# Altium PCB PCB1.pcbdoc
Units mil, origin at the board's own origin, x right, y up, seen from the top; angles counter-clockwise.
Board outline 3500 x 3430 mil, 2 copper layers (Top Layer, Bottom Layer), stack 62.2 mil thick; 73 components, 57 nets, 244 pads, 134 vias.
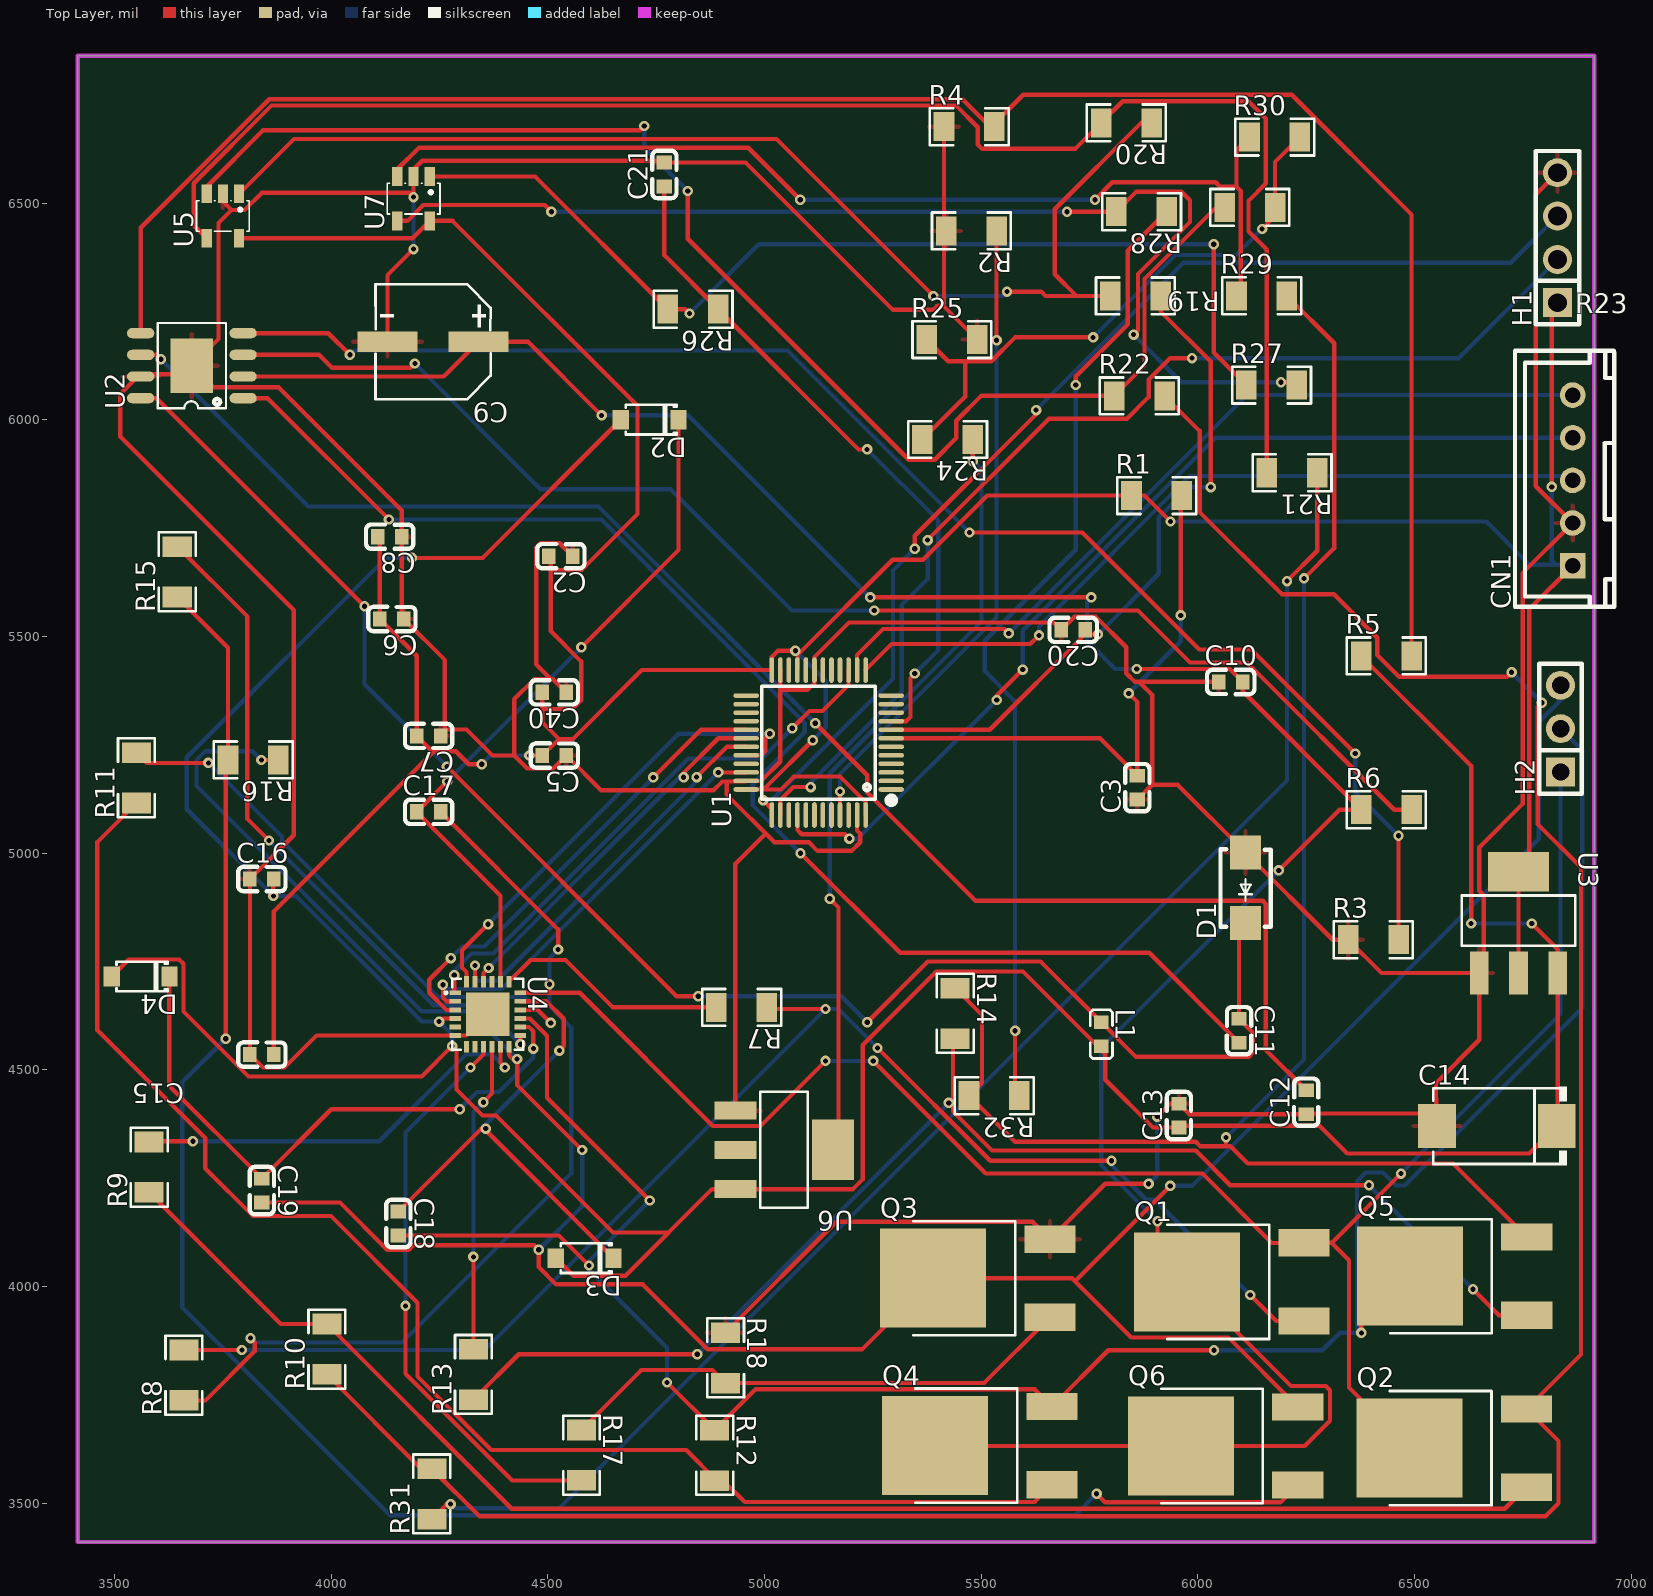
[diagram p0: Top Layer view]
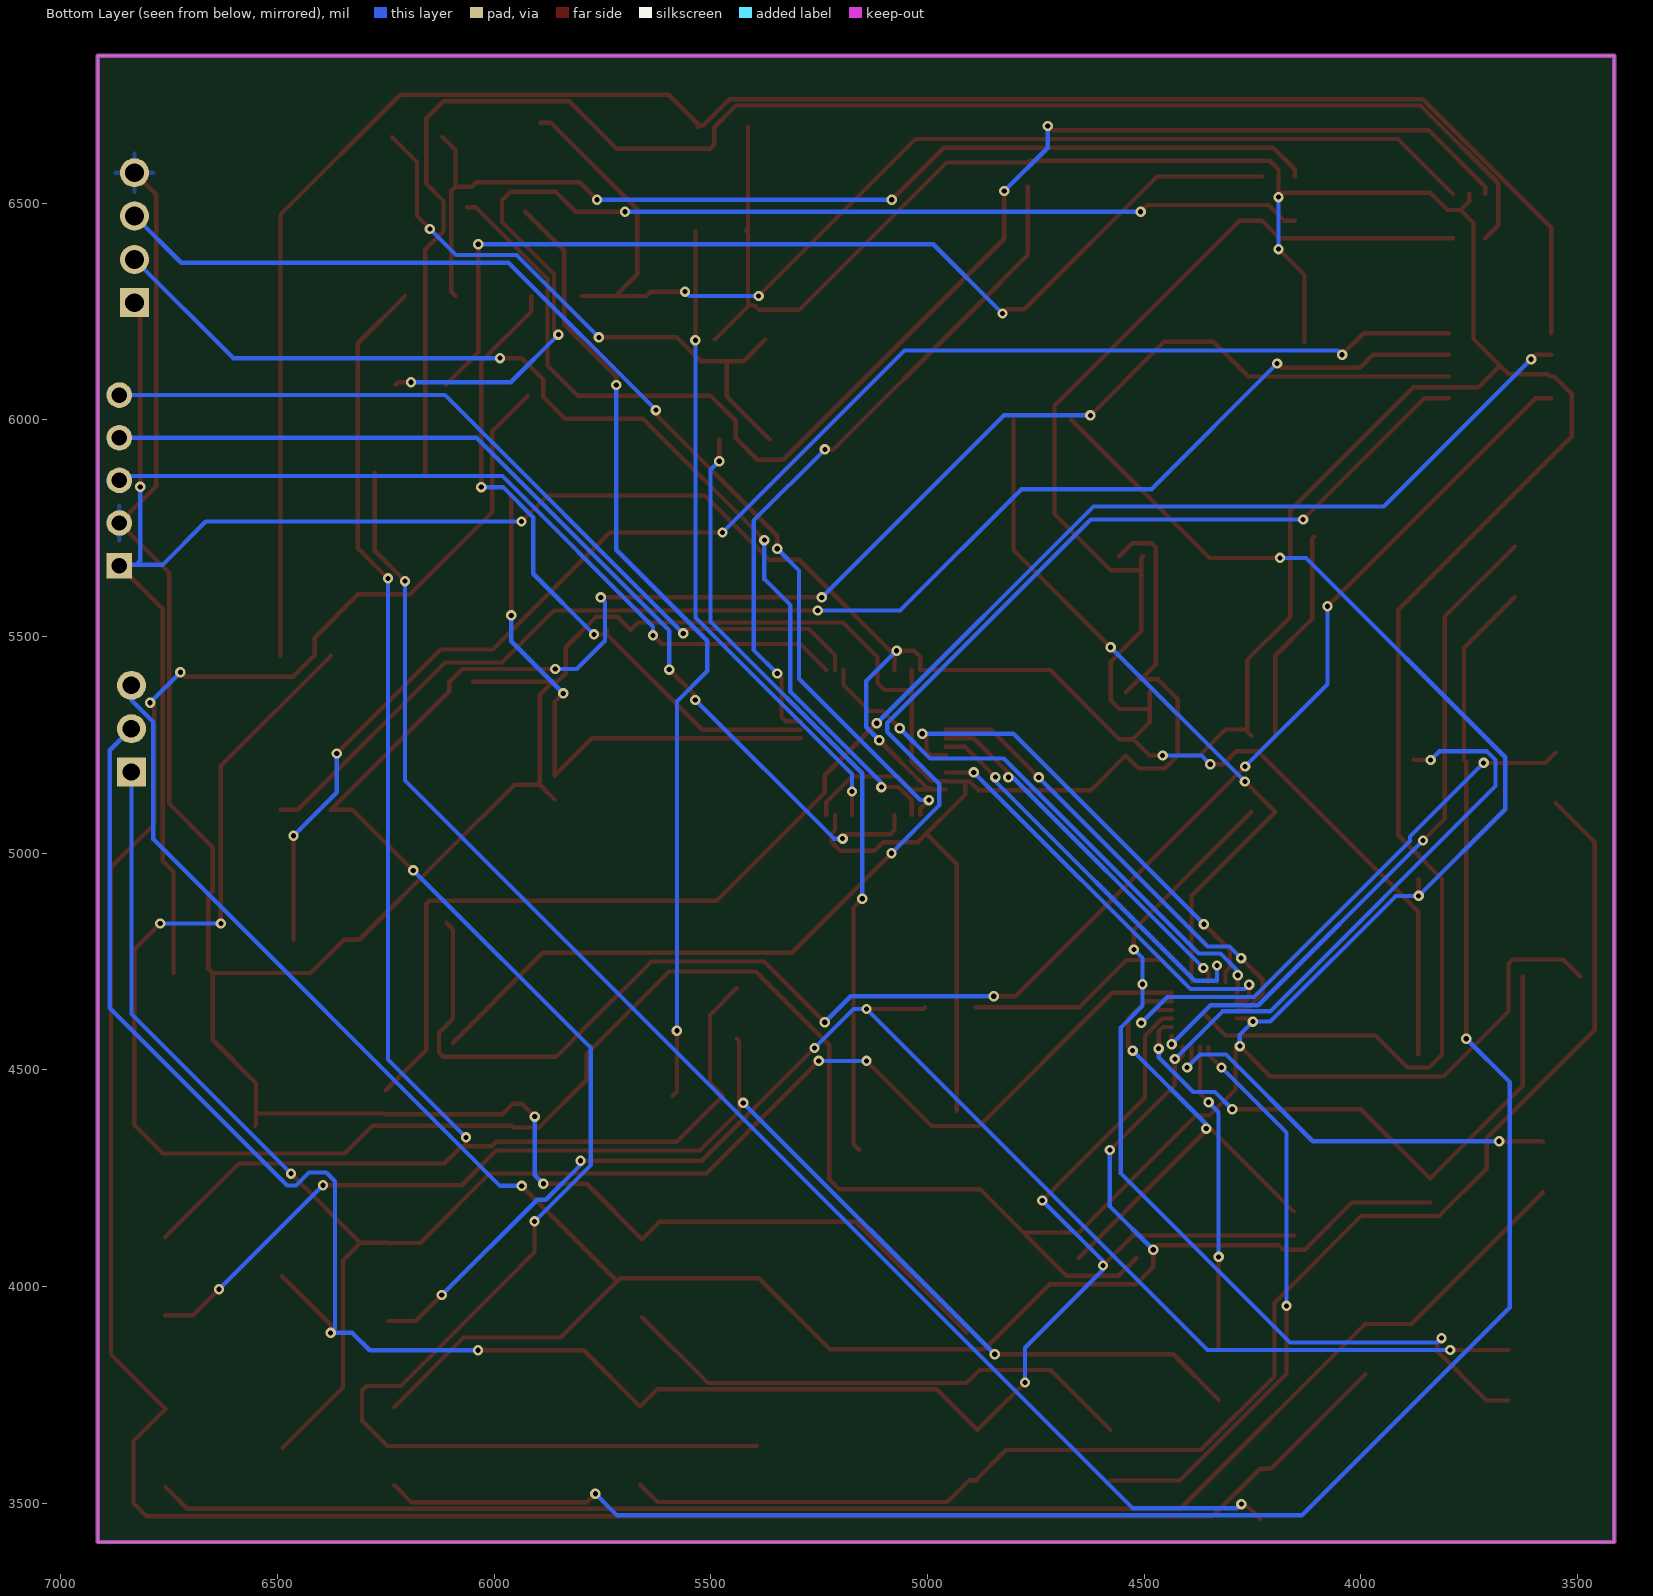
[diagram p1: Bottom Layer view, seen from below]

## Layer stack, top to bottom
Top Solder Mask Layer: solder mask 0.4, Dk 3.3
Top Layer: signal copper 1.4
Dielectric1: surface 59.4, FR4, Dk 4.5
Bottom Layer: signal copper 1.4
Bottom Solder Mask Layer: solder mask 0.4, Dk 3.3

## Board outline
3415,6840 3415,3410 6915,3410 6915,6840

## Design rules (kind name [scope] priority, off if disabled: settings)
BoardOutlineClearance copperThickness1oz [All] p0: genericclearance=10 ignorepadtopadclearanceinfootprint=FALSE except(0: Arc-SplitContinuation Track-SplitContinuation SMDPad-SplitContinuation THPad-SplitContinuation Via-SplitContinuation Fill-SplitContinuation Poly-SplitContinuation Region-SplitContinuation Text-SplitContinuation)
BoardOutlineClearance copperThickness2oz [All] p0: genericclearance=10 ignorepadtopadclearanceinfootprint=FALSE except(0: Arc-SplitContinuation Track-SplitContinuation SMDPad-SplitContinuation THPad-SplitContinuation Via-SplitContinuation Fill-SplitContinuation Poly-SplitContinuation Region-SplitContinuation Text-SplitContinuation)
BoardOutlineClearance otherClearance [All] p0: genericclearance=10 ignorepadtopadclearanceinfootprint=FALSE except(0: Arc-SplitContinuation Track-SplitContinuation SMDPad-SplitContinuation THPad-SplitContinuation Via-SplitContinuation Fill-SplitContinuation Poly-SplitContinuation Region-SplitContinuation Text-SplitContinuation)
Clearance copperThickness1oz [All] p1: gap=7 ignorepadtopadclearanceinfootprint=FALSE
Clearance copperThickness2oz [All] p1: gap=7 ignorepadtopadclearanceinfootprint=FALSE
Clearance otherClearance [All] p1: gap=7 ignorepadtopadclearanceinfootprint=FALSE
DiffPairsRouting differentialPair [All] p1: maxuncoupledlength=10 minlimit=6 maxlimit=Infinity mostfreqgap=6 toplayer_minwidth=5 toplayer_prefwidth=10 toplayer_maxwidth=100 bottomlayer_minwidth=5 bottomlayer_prefwidth=10 bottomlayer_maxwidth=100
PasteMaskExpansion pasteMaskExpansion [All] p1: expansion=0
PlaneConnect innerPlane [All] p1: planeconnectstyle=Relief reliefexpansion=20 reliefentries=4 reliefconductorwidth=10 reliefairgap=10
PolygonConnect copperRegion [All] p1: connectstyle=Relief reliefentries=4 reliefconductorwidth=10 polygonreliefangle="90 Angle" airgapwidth=10
RoutingVias viaSize [All] p1: viastyle="Through Hole" holewidth=12.0078 minholewidth=11.811 maxholewidth=248.0314 width=12.0078 minwidth=11.811 maxwidth=248.0314
SolderMaskExpansion solderMaskExpansion [IsVia] p1: useseparateexpansions=TRUE expansion=-1000 expansionbottom=-1000
SolderMaskExpansion solderMaskExpansion [All] p2: useseparateexpansions=TRUE expansion=2 expansionbottom=2
Width copperThickness1oz [All] p1: maxlimit=100 minlimit=5 preferedwidth=10
Width copperThickness2oz [All] p1: maxlimit=100 minlimit=8 preferedwidth=10

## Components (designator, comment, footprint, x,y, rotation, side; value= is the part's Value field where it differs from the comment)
C2 "100nF" C0603#1 4530,5685 r180 top
C3 "100nF" C0603#2 5860.4,5150.9 r90 top
C5 "100nF" C0603#1 4515,5225 r180 top
C6 "100nF" C0603#1 4140,5540 r180 top
C7 "100nF" C0603#1 4224.8,5270.2 r180 top
C8 "100nF" C0603#1 4135,5730 r180 top
C9 "100uF" CAP-SMD_BD6.3-L6.6-W6.6-LS7.3-FD-H7.7 4235,6180 r180 top
C10 "100nF" C0603#3 6076,5394.8 r0 top
C11 "100nF" C0603#1 6095,4590 r270 top
C12 "100nF" C0603#1 6250,4425 r90 top
C13 "100nF" C0603#2 5956.3,4394.1 r90 top
C14 "220uF" CAP-SMD_L7.3-W4.3-RD 6690,4370 r0 top
C15 "100nF" C0603#1 3840,4535 r180 top
C16 "100nF" C0603#1 3840,4940 r0 top
C17 "100nF" C0603#1 4225,5095 r0 top
C18 "100nF" C0603#1 4155,4145 r270 top
C19 "100nF" C0603#1 3840,4221.1 r270 top
C20 "100nF" C0603#3 5712.4,5515 r180 top
C21 "100nF" C0603#3 4768.9,6565.9 r90 top
C40 "100nF" C0603#1 4514.8,5370.8 r180 top
CN1 "WAFER-XH254Z-5AL" CONN-TH_5P-P2.50_WAFER-XH254Z-5A 6865,5860 r90 top
D1 "SS34-E" SMA_L4.2-W2.6-LS5.0-RD 6110,4920 r90 top
D2 "1N4148W-E3-08" SOD-123_L2.8-W1.8-LS3.7-RD 4735,6000 r180 top
D3 "1N4148W-E3-08" SOD-123_L2.8-W1.8-LS3.7-RD 4585,4065 r180 top
D4 "1N4148W-E3-08" SOD-123_L2.8-W1.8-LS3.7-RD 3560,4715 r180 top
H1 "PZ254V-11-04P" HDR-TH_4P-P2.54-V-M 6830,6420 r90 top
H2 "PZ254V-11-03P" HDR-TH_3P-P2.54-V-M_PZ254V-11-03P 6837,5287 r90 top
L1 "10uH" L0603 5777.3,4582 r270 top
Q1 "NCEP40T11K" TO-252-2_L6.6-W6.1-P4.57-LS9.9-BR-CW#1 6109.9,4010.1 r0 top
Q2 "NCEP40T11K" TO-252-2_L6.6-W6.1-P4.57-LS9.9-BR-CW#2 6623.3,3626.8 r0 top
Q3 "NCEP40T11K" TO-252-2_L6.6-W6.1-P4.57-LS9.9-BR-CW#3 5523.8,4018.8 r0 top
Q4 "NCEP40T11K" TO-252-2_L6.6-W6.1-P4.57-LS9.9-BR-CW#2 5528.5,3632.4 r0 top
Q5 "NCEP40T11K" TO-252-2_L6.6-W6.1-P4.57-LS9.9-BR-CW#2 6624.1,4023.5 r0 top
Q6 "NCEP40T11K" TO-252-2_L6.6-W6.1-P4.57-LS9.9-BR-CW#2 6095.7,3631.6 r0 top
R1 "0Ω" R1206#1 5905,5825 r0 top
R2 "0Ω" R1206#1 5477.4,6435.6 r180 top
R3 "0Ω" R1206#1 6405,4800 r0 top
R4 "0Ω" R1206#1 5472.4,6676.3 r0 top
R5 "0Ω" R1206#1 6435,5455 r0 top
R6 "0Ω" R1206#1 6435,5100 r0 top
R7 "0Ω" R1206#2 4947.2,4643.8 r180 top
R8 "0Ω" R1206#1 3660,3795 r90 top
R9 "0Ω" R1206#1 3580,4275 r90 top
R10 "0Ω" R1206#1 3990,3855 r90 top
R11 "0Ω" R1206#1 3550.4,5173.6 r90 top
R12 "0Ω" R1206#1 4885,3610 r270 top
R13 "0Ω" R1206#1 4328.2,3796.8 r90 top
R14 "0Ω" R1206#1 5440,4630 r270 top
R15 "0Ω" R1206#1 3644.7,5649.1 r90 top
R16 "0Ω" R1206#1 3820,5215 r180 top
R17 "0Ω" R1206#2 4577.6,3610.3 r270 top
R18 "0Ω" R1206#1 4910,3835 r270 top
R19 "0Ω" R1206#1 5855.9,6285.6 r180 top
R20 "0Ω" R1206#1 5835,6685 r180 top
R21 "0Ω" R1206#1 6217.4,5877.6 r180 top
R22 "0Ω" R1206#1 5865,6055 r0 top
R23 "0Ω" R1206#1 6120,6490 r0 top
R24 "0Ω" R1206#1 5422.4,5954.3 r180 top
R25 "0Ω" R1206#1 5432.4,6185 r0 top
R26 "0Ω" R1206#1 4835,6255 r180 top
R27 "0Ω" R1206#1 6170,6080 r0 top
R28 "0Ω" R1206#1 5870,6480 r180 top
R29 "0Ω" R1206#1 6147.4,6285.8 r0 top
R30 "0Ω" R1206#1 6177.4,6652.1 r0 top
R31 "0Ω" R1206#3 4232.1,3521 r90 top
R32 "0Ω" R1206#1 5530,4440 r180 top
U1 "STM32G431C8T6" LQFP-48_L7.0-W7.0-P0.50-LS9.0-BL 5125,5255 r90 top
U2 "LMR14030SDDAR" SO-8_L4.9-W3.9-P1.27-LS6.0-BL-EP 3678.5,6124.7 r90 top
U3 "AMS1117-3.3" SOT-223-3_L6.5-W3.4-P2.30-LS7.0-BR 6740,4840 r270 top
U4 "FD6288Q" QFN-24_L4.0-W4.0-P0.50-BL-EP2.6 4361.4,4628.2 r270 top
U5 "AD8628ARTZ-REEL7" SOT-23-5_L3.0-W1.7-P0.95-LS2.8-BR 3750,6470 r90 top
U6 "AMS1117-5.0" SOT-223_L6.5-W3.5-P2.30-LS7.0-BR 5045,4315 r180 top
U7 "AD8628ARTZ-REEL7" SOT-23-5_L3.0-W1.7-P0.95-LS2.8-BR 4190,6510 r90 top

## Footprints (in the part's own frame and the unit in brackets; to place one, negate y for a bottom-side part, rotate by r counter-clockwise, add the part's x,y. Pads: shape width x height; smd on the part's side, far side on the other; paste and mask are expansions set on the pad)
C0603#1 [mil]
  rect 31.5x35.4 smd: 1(-27.6,0) 2(27.6,0)
  silkscreen extent -55,-28 55,28
C0603#2 [mil]
  rect 31.5x35.4 smd: 1(-27.5,0) 2(27.6,0)
  silkscreen extent -55,-28 55,28
C0603#3 [mil]
  rect 31.5x35.4 smd: 1(-27.6,0) 2(27.5,0)
  silkscreen extent -55,-28 55,28
CAP-SMD_BD6.3-L6.6-W6.6-LS7.3-FD-H7.7 [mil]
  rect 137.8x47.2 smd: 1(-105.1,0) 2(105.1,0)
  silkscreen extent -133,-133 133,133
CAP-SMD_L7.3-W4.3-RD [mil]
  rect 86.9x102 smd: 1(138.2,0) 2(-138.2,0)
  silkscreen extent -147,-91 162,91
CONN-TH_5P-P2.50_WAFER-XH254Z-5A [mil]
  rect 59.1x59.1 hole 35.4 paste+0 mask+2: 1(-196.9,0)
  round 59.1 hole 35.4 paste+0 mask+2: 2(-98.4,0) 3(0,0) 4(98.4,0) 5(196.8,0)
  silkscreen extent -292,-96 299,133
HDR-TH_3P-P2.54-V-M_PZ254V-11-03P [mil]
  rect 66.9x66.9 hole 40.2: 1(-100,0)
  round 66.9 hole 40.2: 2(0,0) 3(100,0)
  silkscreen extent -150,-49 150,49
HDR-TH_4P-P2.54-V-M [mil]
  rect 66.9x66.9 hole 43.3: 1(-150,0)
  round 66.9 hole 43.3: 2(-50,0) 3(50,0) 4(150,0)
  silkscreen extent -200,-50 200,50
L0603 [mil]
  rect 31.5x34 smd paste-3937 mask+2: 1(-27.5,0) 2(27.6,0)
  silkscreen extent -56,-26 56,26
LQFP-48_L7.0-W7.0-P0.50-LS9.0-BL [mil]
  oval 10.6x59.1 smd paste+0 mask+2: 1(-108.3,-167.3) 2(-88.6,-167.3) 3(-68.9,-167.3) 4(-49.2,-167.3) 5(-29.5,-167.3) 6(-9.8,-167.3) 7(9.8,-167.3) 8(29.5,-167.3) 9(49.2,-167.3) 10(68.9,-167.3) 11(88.6,-167.3) 12(108.3,-167.3) 25(108.3,167.3) 26(88.6,167.3) 27(68.9,167.3) 28(49.2,167.3) 29(29.5,167.3) 30(9.8,167.3) 31(-9.8,167.3) 32(-29.5,167.3) 33(-49.2,167.3) 34(-68.9,167.3) 35(-88.6,167.3) 36(-108.3,167.3)
  oval 59.1x10.6 smd paste+0 mask+2: 13(167.3,-108.3) 14(167.3,-88.6) 15(167.3,-68.9) 16(167.3,-49.2) 17(167.3,-29.5) 18(167.3,-9.8) 19(167.3,9.8) 20(167.3,29.5) 21(167.3,49.2) 22(167.3,68.9) 23(167.3,88.6) 24(167.3,108.3) 37(-167.3,108.3) 38(-167.3,88.6) 39(-167.3,68.9) 40(-167.3,49.2) 41(-167.3,29.5) 42(-167.3,9.8) 43(-167.3,-9.8) 44(-167.3,-29.5) 45(-167.3,-49.2) 46(-167.3,-68.9) 47(-167.3,-88.6) 48(-167.3,-108.3)
  silkscreen extent -141,-176 130,132
QFN-24_L4.0-W4.0-P0.50-BL-EP2.6 [mil]
  rect 11x26.2 smd paste-3937 mask+2: 1(-49.2,-75.1) 2(-29.5,-75.1) 3(-9.8,-75.1) 4(9.9,-75.1) 5(29.6,-75.1) 6(49.3,-75.1) 13(49.3,75.1) 14(29.6,75.1) 15(9.9,75.1) 16(-9.8,75.1) 17(-29.5,75.1) 18(-49.2,75.1)
  rect 26.2x11 smd paste-3937 mask+2: 7(75.1,-49.3) 8(75.1,-29.6) 9(75.1,-9.9) 10(75.1,9.8) 11(75.1,29.5) 12(75.1,49.2) 19(-75.1,49.2) 20(-75.1,29.5) 21(-75.1,9.8) 22(-75.1,-9.9) 23(-75.1,-29.6) 24(-75.1,-49.3)
  rect 100.4x100.4 smd paste-3937 mask+2: 25(0,0)
  silkscreen extent -82,-100 82,82
R1206#1 [mil]
  rect 47.5x67 smd paste-3937 mask+2: 1(-58.2,0) 2(58.2,0)
  silkscreen extent -91,-42 91,42
R1206#2 [mil]
  rect 47.5x67 smd paste-3937 mask+2: 1(-58.3,0) 2(58.2,0)
  silkscreen extent -91,-43 91,42
R1206#3 [mil]
  rect 47.5x67 smd paste-3937 mask+2: 1(-58.2,0) 2(58.3,0)
  silkscreen extent -91,-43 91,43
SMA_L4.2-W2.6-LS5.0-RD [mil]
  rect 78.7x70.9 smd: 1(-81.1,0) 2(81.1,0)
  silkscreen extent -90,-58 89,58
SO-8_L4.9-W3.9-P1.27-LS6.0-BL-EP [mil]
  oval 23.6x63 smd: 1(-75,-118.1) 2(-25,-118.1) 3(25,-118.1) 4(75,-118.1) 5(75,118.1) 6(25,118.1) 7(-25,118.1) 8(-75,118.1)
  rect 126x98.4 smd: 9(0,0)
  silkscreen extent -98,-79 98,79
SOD-123_L2.8-W1.8-LS3.7-RD [mil]
  rect 37.4x45.3 smd: 1(-66.6,0) 2(66.6,0)
  silkscreen extent -62,-34 55,34
SOT-23-5_L3.0-W1.7-P0.95-LS2.8-BR [mil]
  rect 43.3x23.6 smd: 1(51.2,-37.4) 2(51.2,0) 3(51.2,37.4) 4(-51.2,37.4) 5(-51.2,-37.4)
  silkscreen extent -35,-61 35,61
SOT-223-3_L6.5-W3.4-P2.30-LS7.0-BR [mil]
  rect 98.4x43.3 smd: 1(116.9,-90.6) 2(116.9,0) 3(116.9,90.6)
  rect 92.1x141.7 smd: 4(-116.9,0)
  silkscreen extent -62,-131 54,131
SOT-223_L6.5-W3.5-P2.30-LS7.0-BR [mil]
  rect 97x41.3 smd: 1(112.5,-90.6) 2(112.5,0) 3(112.5,90.6)
  rect 97x139.4 smd: 4(-112.5,0)
  silkscreen extent -55,-134 55,134
TO-252-2_L6.6-W6.1-P4.57-LS9.9-BR-CW#1 [mil]
  rect 118.1x63 smd: 1(134.9,-90.1) 3(134.9,90.2)
  rect 244.1x228.3 smd: 2(-134.8,0)
  silkscreen extent -180,-132 54,132
TO-252-2_L6.6-W6.1-P4.57-LS9.9-BR-CW#2 [mil]
  rect 118.1x63 smd: 1(134.8,-90.1) 3(134.8,90.2)
  rect 244.1x228.3 smd: 2(-134.8,0)
  silkscreen extent -180,-132 54,132
TO-252-2_L6.6-W6.1-P4.57-LS9.9-BR-CW#3 [mil]
  rect 118.1x63 smd: 1(134.8,-90.2) 3(134.8,90.1)
  rect 244.1x228.3 smd: 2(-134.8,0)
  silkscreen extent -180,-132 54,132

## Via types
v1: diameter 24, hole 12, Top Layer to Bottom Layer, 134 vias

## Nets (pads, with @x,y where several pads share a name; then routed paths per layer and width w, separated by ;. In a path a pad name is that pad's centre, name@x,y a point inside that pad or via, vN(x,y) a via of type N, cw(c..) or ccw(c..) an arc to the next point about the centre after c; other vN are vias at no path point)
1.65V: R23.2 R24.2 R25.1 R30.2 | length 1391.1
  Top Layer w10: R24.2 5463.2,6053.3 5463.2,6135 ; R25.1 5424.2,6135 5523.2,6135 5578.2,6190 v1(5758.2,6190) ; v1(6148.2,6440) 6178.2,6470 R23.2 6178.2,6594.8 R30.2
  Bottom Layer w10: v1(5758.2,6190) 5948.2,6380 6088.2,6380 v1(6148.2,6440)
3.3V: C2.2 C5.2 C6.2 C7.2 C8.2 C15.1 C40.2 CN1.1 H1.1 R1.1 U1.21 U1.24 U1.36 U1.48 U3.2 U3.4 U5.5 U7.5 | length 9010
  Top Layer w9.8: C5.2 4524.8,5262.3 4556.7,5262.3 4716.7,5422.3 U1.24 5016.7,5452.3 5031.2,5466.8 5065.8,5466.8 v1@5075.8,5456.8 ; U1.36 4987.7,5146.7 ; v1@5061.2,5466.8 v1(5071.2,5466.8) ; U1.21 v1@5075.8,5456.8 ; v1(5111.2,5260.2) 5001.2,5150.2 4991.2,5150.2 4987.7,5146.7 ; U1.48 5233.3,5117.7 5174.2,5176.7 5067.7,5176.7 5037.7,5146.7 4987.7,5146.7 ; R1.1 5514,5825 5365.8,5676.8 5295.8,5676.8 v1@5075.8,5456.8
  Top Layer w10: U5.5 4187.4,6418.8 U7.5 4280.2,6458.8 4706.7,6032.3 4706.7,5782.3 4576.7,5652.3 4506.7,5652.3 ; C15.1 3867.6,4865.1 4237.4,5235 ; C8.2 4112.4,5725 C6.2 4197.2,5455.2 C7.2 4232.4,5235 4287.4,5235 4317.4,5205 v1(4347.4,5205) ; v1(4457.4,5225) C5.2 ; 4486.7,5332.3 4556.7,5332.3 4576.7,5352.3 4576.7,5442.3 4506.7,5512.3 4506.7,5680.7 C2.2 ; C40.2 4486.7,5370.3 4486.7,5302.3 4526.7,5262.3 ; R1.1 5876.8,5825 v1(5936.8,5765) ; U3.2 U3.4 6765,4981.9 6765,5563.1 CN1.1 ; v1(6816.8,5845) 6816.8,6256.8 H1.1
  Bottom Layer w9.8: v1(5071.2,5466.8) 5141.2,5396.8 5141.2,5290.2 v1(5111.2,5260.2)
  Bottom Layer w10: v1(4347.4,5205) 4367.4,5225 v1(4457.4,5225) ; v1(5936.8,5765) 6665.4,5765 6765.4,5665 6863.2,5665 CN1.1 ; v1(6816.8,5845) 6816.8,5675 6826.8,5665
12V: C13.1 C14.1 C16.2 D2.2 D3.2 D4.2 L1.2 R5.1 U3.3 U4.4 U6.3 | length 8519
  Top Layer w9.9: v1(3866.5,4901) 3866.5,4939 C16.2 ; v1(4249,4611) 4256.3,4618.3 U4.4 ; v1(4279,4554.4) 4289,4544.4 4289,4454.4 4349,4394.4 4380.2,4394.4 4650.2,4124.4 4779,4124.4
  Top Layer w10: D4.2 3532.8,4754.4 3649,4754.4 3659,4744.4 3659,4634.4 3809,4484.4 4209,4484.4 v1(4279,4554.4) ; v1(4186.5,5681) 4349.4,5681 D2.2 ; D3.2 4558.9,4024.4 4679,4024.4 4879,4224.4 U6.3 5204.1,4224.4 5226.3,4246.6 5226.3,4556.6 5396.3,4726.6 5596.3,4726.6 L1.2@5776.3,4546.6 ; L1.2 5776.3,4553.4 L1.2@5776.3,4546.6 ; R5.1 6630.6,5201.2 v1(6630.6,4837.3) ; v1(6770.6,4837.3) 6830.6,4777.3 U3.3 6830.6,4372.3 C14.1 6764.8,4306.6 6344.8,4306.6 6280.9,4370.6 5960.2,4370.6 C13.1 5896.3,4366.6 5786.3,4476.6 5786.3,4536.6 L1.2@5776.3,4546.6
  Bottom Layer w9.9: v1(3866.5,4901) 3919,4901 4209,4611 v1(4249,4611) 4279,4581 v1(4279,4554.4)
  Bottom Layer w10: v1(3866.5,4901) 3666.5,5101 3666.5,5221 4126.5,5681 v1(4186.5,5681) ; v1(6630.6,4837.3) v1(6770.6,4837.3)
24V: C9.1 C10.2 Q1.2 Q4.2 Q6.2 R6.1 U2.2 | length 6035.5
  Top Layer w10: U2.2 4259.8,6099.7 C9.1 4454,6180 v1(4624,6010) ; v1(5244,5590) v1(5754,5590) ; Q4.2 5394.5,3631.6 Q6.2 6246.6,3631.6 6305.1,3690.1 6305.1,3760.1 6295.1,3770.1 6215.1,3770.1 Q1.2 5906.8,4078.5 v1(5906.8,4150) ; v1(5859.2,5424.8) 6073.5,5424.8 C10.2 6103.5,5373.3 R6.1 6326.8,5100 v1(6186.8,4960)
  Bottom Layer w10: v1(4624,6010) 4824,6010 v1(5244,5590) ; v1(5754,5590) 5744,5580 5744,5490 5809.2,5424.8 v1(5859.2,5424.8) ; v1(5906.8,4150) 5776.8,4280 5776.8,4550 v1(6186.8,4960)
$1N13: C3.2 R1.2 U1.7 | length 1309.5
  Top Layer w9.8: U1.7 5774.1,5264.8 C3.2
  Top Layer w10: v1(5840.4,5368.5) 5860.4,5348.5 C3.2 ; v1(5960.4,5548.5) 5960.4,5822.2 R1.2
  Bottom Layer w10: v1(5840.4,5368.5) 5960.4,5488.5 v1(5960.4,5548.5)
$1N16: R2.1 U1.45 | length 1497.6
  Top Layer w9.8: U1.45 v1(5174.2,5142.1) ; v1(5535.6,6183.5) R2.1
  Bottom Layer w9.8: v1(5174.2,5142.1) 5174.2,5182.1 5535.6,5543.5 v1(5535.6,6183.5)
$1N28: C11.1 D1.1 L1.1 U2.8 | length 3741.1
  Top Layer w10: U2.8 3596.9,6049.7 v1(4076.9,5569.7) ; v1(4266.9,5199.7) 4796.9,4669.7 v1(4846.9,4669.7) ; v1(5236.9,4609.7) 5376.9,4749.7 5637.1,4749.7 L1.1 5857.3,4529.5 6117.3,4529.5 6127.3,4539.5 6127.3,4585.3 C11.1 6095,4823.9 D1.1
  Bottom Layer w10: v1(4076.9,5569.7) 4076.9,5389.7 v1(4266.9,5199.7) ; v1(4846.9,4669.7) 5176.9,4669.7 v1(5236.9,4609.7)
$1N31: C11.2 U2.1 | length 3195.5
  Top Layer w10: U2.1 3853.1,6049.7 v1(4133.1,5769.7) ; v1(5083.1,4999.7) 5313.1,4769.7 5887.7,4769.7 C11.2
  Bottom Layer w10: v1(4133.1,5769.7) 4623.1,5769.7 5093.1,5299.7 5093.1,5279.7 4973.1,5159.7 4973.1,5109.7 v1(5083.1,4999.7)
$1N32: R6.2 U2.3 | length 3139.9
  Top Layer w10: U2.3 3971.8,6149.7 4001.8,6119.7 4183.1,6119.7 v1(4193.1,6129.7) ; v1(5253.1,5559.7) 5861.8,5559.7 5981.8,5439.7 6113.1,5439.7 6453.1,5099.7 6492.9,5099.7 R6.2
  Bottom Layer w10: v1(4193.1,6129.7) 4483.1,5839.7 4783.1,5839.7 5063.1,5559.7 v1(5253.1,5559.7)
$1N34: R3.2 U2.4 | length 3447.6
  Top Layer w10: U2.4 3993.1,6199.7 v1(4043.1,6149.7) ; v1(5473.1,5739.7) 5733.1,5739.7 6003.1,5469.7 6123.1,5469.7 v1(6363.1,5229.7) ; R3.2@6463.1,4800.1 v1(6463.1,5039.7)
  Bottom Layer w10: v1(4043.1,6149.7) 4053.1,6159.7 5053.1,6159.7 v1(5473.1,5739.7) ; v1(6363.1,5229.7) 6363.1,5139.7 v1(6463.1,5039.7)
$1N36: C12.2 U2.6 | length 3613.3
  Top Layer w10: U2.6 3596.9,6149.7 v1(3606.9,6139.7) ; v1(5116.9,5299.7) 5236.9,5179.7 5236.9,5139.7 5486.9,4889.7 6149.7,4889.7 6156.9,4882.5 6156.9,4545.7 C12.2
  Bottom Layer w10: v1(3606.9,6139.7) 3946.9,5799.7 4616.9,5799.7 v1(5116.9,5299.7)
$1N80: Q1.1 R7.1 R8.2 | length 3351.6
  Top Layer w10: R8.2 v1(3793.9,3853.2) ; R7.1 5009.3,4640 v1(5140.7,4640) ; v1(5260.7,4550) 5520.7,4290 v1(5800.7,4290) ; v1(6120.7,3980) 6180.7,3920 Q1.1
  Bottom Layer w10: v1(3793.9,3853.2) 4353.9,3853.2 v1(5140.7,4640) 5170.7,4640 v1(5260.7,4550) ; v1(5800.7,4290) 5800.7,4280 5880.7,4200 5900.7,4200 v1(6120.7,3980)
$1N82: Q2.1 R9.1 R10.2 | length 3501.2
  Top Layer w10: R9.1 3883.6,3913.2 R10.2 4416.5,3486.7 6708.1,3486.7 Q2.1
$1N83: Q4.1 R11.1 R12.2 | length 3376.9
  Top Layer w10: R11.1 3460.4,5025.4 3460.4,4591.1 3709.2,4342.3 3709.2,4272.3 3819.2,4162.3 3999.2,4162.3 4199.2,3962.3 4199.2,3792.3 4369.2,3622.3 4819.2,3622.3 R12.2@4889.2,3552.3 ; R12.2 R12.2@4889.2,3552.3 ; Q4.1 5623.3,3502.3 4954.3,3502.3 4904.3,3552.3 R12.2@4889.2,3552.3
$1N84: Q5.1 R13.1 R14.2 | length 3079.5
  Top Layer w10: R13.1 4433,3843.4 v1(4844.9,3843.4) ; v1(5424.9,4423.4) v1@5434.9,4423.4 ; R14.2 5434.9,4566.6 5434.9,4403.4 5524.9,4313.4 5994.9,4313.4 6074.9,4233.4 v1(6394.9,4233.4) ; v1(6634.9,3993.4) 6694.9,3933.4 Q5.1
  Bottom Layer w10: v1(4844.9,3843.4) v1(5424.9,4423.4) ; v1(6394.9,4233.4) v1(6634.9,3993.4)
$1N85: Q6.1 R15.1 R16.2 | length 4550.2
  Top Layer w10: R15.1 3761.8,5473.8 R16.2 3756.4,5209.7 v1(3756.4,4571.4) ; v1(5766.4,3521.4) 5786.4,3501.4 6190.5,3501.4 Q6.1@6230.5,3541.4
  Bottom Layer w10: v1(3756.4,4571.4) 3656.4,4471.4 3656.4,3951.4 4136.4,3471.4 5716.4,3471.4 v1(5766.4,3521.4)
$1N86: Q3.1 R17.1 R18.2 | length 1213.5
  Top Layer w10: R17.1 4715.8,3806.8 4880,3806.8 R18.2 5506.8,3776.8 Q3.1
$1N110: R19.2 R20.1 U5.1 | length 2747.9
  Top Layer w10: U5.1 3914.1,6647.8 5027.4,6647.8 v1(5389.6,6285.6) ; v1(5559.6,6295.6) 5638.4,6295.6 5648.4,6285.6 R19.2 ; 5719.6,6285.6 5669.6,6335.6 5669.6,6485.6 5869,6685 R20.1
  Bottom Layer w10: v1(5389.6,6285.6) 5549.6,6285.6 v1(5559.6,6295.6)
$1N113: R20.2 R21.2 U5.4 | length 3666.2
  Top Layer w10: U5.4 3682.6,6448.8 3682.6,6545.5 3862.1,6725 5442.1,6725 5492.1,6675 5492.1,6635 5502.1,6625 5716.8,6625 R20.2 5826.8,6735 6116.8,6735 6156.8,6695 6156.8,6545 6116.8,6505 6116.8,6435 6159.2,6392.6 R21.2
$1N115: R22.1 R23.1 U5.3 | length 3218.2
  Top Layer w10: U5.3 3712.6,6537.8 3842.6,6667.8 4712.6,6667.8 v1(4722.6,6677.8) ; v1(4822.6,6527.8) 4822.6,6417.8 5332.6,5907.8 5392.6,5907.8 5442.6,5957.8 5442.6,5997.8 5499.8,6055 R22.1 5876.8,6125 5876.8,6325 6041.8,6490 R23.1
  Bottom Layer w10: v1(4722.6,6677.8) 4722.6,6627.8 v1(4822.6,6527.8)
$1N119: R24.1 U6.4 | length 1806.3
  Top Layer w10: v1(5150.6,4894.3) 5170.6,4874.3 5170.6,4328.1 U6.4 ; v1(5480.6,5904.3) R24.1
  Bottom Layer w10: v1(5150.6,4894.3) 5150.6,5184.3 5500.6,5534.3 5500.6,5884.3 v1(5480.6,5904.3)
$1N126: R29.1 R30.1 U7.3 | length 2431.3
  Top Layer w10: U7.3 4152.6,6577.8 4202.6,6627.8 4962.6,6627.8 v1(5082.6,6507.8) ; v1(5762.6,6507.8) 5802.6,6547.8 6041.3,6547.8 6051.3,6537.8 6089.2,6537.8 ; R29.1 6099.2,6295.8 6099.2,6527.8 6089.2,6537.8 ; R30.1 6089.2,6622.1 6089.2,6537.8
  Bottom Layer w10: v1(5082.6,6507.8) v1(5762.6,6507.8)
$1N128: R27.2 R28.2 U7.4 | length 2666.8
  Top Layer w10: U7.4 4175.9,6458.8 4212.6,6495.5 4492.6,6495.5 v1(4508.1,6480) ; v1(5698.1,6480) R28.2 5858.2,6526.4 5961.8,6526.4 5981.8,6506.4 5981.8,6456.4 5861.8,6336.4 5861.8,6206.4 v1(5851.8,6196.4) ; v1(6191.8,6086.4) 6221.8,6086.4 R27.2
  Bottom Layer w10: v1(4508.1,6480) v1(5698.1,6480) ; v1(5851.8,6196.4) 5961.8,6086.4 v1(6191.8,6086.4)
$1N131: R26.2 R27.1 U7.1 | length 2362.7
  Top Layer w10: U7.1 4470.6,6561.2 R26.2 4816.8,6255 v1(4826.8,6245) ; v1(6036.8,6405) 6036.8,6155 R27.1
  Bottom Layer w10: v1(4826.8,6245) 4986.8,6405 v1(6036.8,6405)
CUR_U_GND: R21.1 R31.1 | length 3426.9
  Top Layer w10: R31.1 4266.9,3497.6 v1(4275.6,3497.6) ; v1(6205.6,5627.6) 6275.6,5697.6 R21.1
  Bottom Layer w10: v1(4275.6,3497.6) 4285.6,3487.6 4525.6,3487.6 6205.6,5167.6 v1(6205.6,5627.6)
CUR_V_GND: R28.1 R32.1 | length 2247.1
  Top Layer w10: v1(5578.2,4590) 5578.2,4450 R32.1 ; v1(5718.2,6080) 5718.2,6100 5838.2,6220 5838.2,6390 R28.1
  Bottom Layer w10: v1(5578.2,4590) 5578.2,5350 5508.2,5420 5508.2,5490 5718.2,5700 v1(5718.2,6080)
FB: R4.2 R5.2 U2.5 | length 4490.8
  Top Layer w10: U2.5 3560.4,6443.2 3856.9,6739.7 5456.9,6739.7 5516.9,6679.7 R4.2@5526.9,6679.7 ; R4.2 R4.2@5526.9,6679.7 ; R5.2 6493.2,6473.3 6216.9,6749.7 5596.9,6749.7 R4.2@5526.9,6679.7
GND: C2.1 C3.1 C5.1 C6.1 C7.1 C8.1 C9.2 C10.1 C12.1 C13.2 C14.2 C15.2 C16.1 C20.2 C21.2 C40.1 CN1.2 D1.2 H1.4 Q3.3 R2.2 R3.1 R4.1 R18.1 R25.2 U1.19 U1.23 U1.35 U1.47 U2.7 U2.9 U3.1 U4.6 U4.25 U5.2 U6.1 U7.2 | length 16709.1
  Top Layer w9.8: C5.1 4622.6,5145 4882.6,5145 4902.6,5165 4956.3,5165 U1.35 4992.1,5166.4 5036.4,5210.7 U1.23 ; 4912.6,5165 4912.6,5135 5022.6,5025 5102.6,5025 5122.6,5005 5200.9,5005 5220.9,5025 5220.9,5045 5213.6,5052.3 U1.47 ; 5036.4,5376.4 5099.3,5376.4 5115.2,5392.3 U1.19 5115.2,5452.3 5195.2,5532.3 5667.5,5532.3 C20.2
  Top Layer w9.9: C15.2 3842.4,4505 3892.4,4505 3966.4,4578.9 U4.6 4312.1,4578.9 U4.25
  Top Layer w10: U2.7 U2.7@3563.5,6099.7 ; U5.2 3750,6503.8 3770,6483.8 ; C15.2 C16.1 3913.5,5041.1 3913.5,5560.9 3513.5,5960.9 3513.5,6059.7 3553.5,6099.7 U2.7@3563.5,6099.7 ; C9.2 4129.9,6333.7 v1(4190,6393.8) ; v1(4190,6513.8) U7.2 4190,6577.8 4210,6597.8 4764.5,6597.8 C21.2 4956.4,6593.4 5296.4,6253.4 5388.9,6253.4 5398.9,6263.4 5408.9,6263.4 ; v1@4190,6523.8 3840,6523.8 3800,6483.8 3770,6483.8 ; C7.1@4252.3,5270.2 4262.3,5280.2 4262.3,5445.2 C6.1 4162.6,5545 C8.1 4162.6,5790.6 3878.5,6074.7 3728.5,6074.7 U2.9 ; C7.1@4262.3,5285.2 4312.3,5285.2 4372.3,5225.2 4422.3,5225.2 ; 4507.9,5400.8 4473.4,5435.4 4473.4,5705 4483.4,5715 4527.6,5715 C2.1 ; C40.1@4542.3,5370.8 4512.3,5400.8 4467.9,5400.8 4422.3,5355.2 4422.3,5225.2 ; C5.1 4512.6,5195 4452.6,5195 4422.3,5225.2 ; R18.1 5165.7,4148.9 5618.6,4148.9 Q3.3 5786.3,4236.6 v1(5886.3,4236.6) ; U6.1@4932.5,4405.5 4932.5,4974.9 5002.6,5045 ; R2.2@5414.2,6438.7 5416.1,6438.7 R2.2 ; R4.1 5414.2,6268.7 5408.9,6263.4 ; R25.2 5412.1,6263.4 5408.9,6263.4 ; C20.2 5714.9,5545 5764.9,5545 5834.9,5475 5834.9,5415 5854.9,5395 C10.1@6048.2,5395 ; C3.1 5894.9,5157.8 ; 5864.9,5395 5894.9,5365 5894.9,5157.8 ; v1(5906.3,4391.7) 5936.3,4421.7 C13.2 5980.5,4397.4 C12.1 6251.4,4398.9 C14.2@6549.5,4398.9 ; C14.2 6549.5,4372.3 6549.5,4468.9 6649.5,4568.9 U3.1@6649.5,4723.1 ; H1.4 6780,6520 6780,5846.6 CN1.2 6749.5,5646 6749.5,5113.1 6649.5,5013.1 6649.5,4913.1 6659.5,4903.1 6659.5,4733.1 U3.1@6649.5,4723.1 ; U2.7@3563.5,6099.7 3568.5,6104.7 3658.5,6104.7 U2.9 ; U2.9 3740,6186.2 3740,6453.8 3770,6483.8 ; 5894.9,5157.8 5953.3,5157.8 D1.2 6311.1,4800 R3.1 6423.7,4723.1 U3.1@6649.5,4723.1
  Bottom Layer w10: v1(4190,6393.8) v1(4190,6513.8) ; v1(5886.3,4236.6) 5906.3,4256.6 v1(5906.3,4391.7)
HO1: R7.2 U4.19 | length 544.4
  Top Layer w9.9: U4.19@4410.6,4703.2 4460.6,4753.2 4540.6,4753.2 4650,4643.8 R7.2
HO2: R11.2 U4.16 | length 1302.7
  Top Layer w9.9: R11.2 3574.3,5208 v1(3716.5,5208) ; U4.16 4476.5,4638 v1(4506.5,4608)
  Bottom Layer w9.9: v1(3716.5,5208) 3886.5,5038 3886.5,5028 4246.5,4668 4446.5,4668 v1(4506.5,4608)
HO3: R15.2 U4.13 | length 1560.8
  Top Layer w9.9: R15.2 3806.5,5545.6 3806.5,5078.9 v1(3856.5,5028.9) ; v1(4436.5,4558.9) U4.13
  Bottom Layer w9.9: v1(3856.5,5028.9) 4236.5,4648.9 4346.5,4648.9 v1(4436.5,4558.9)
LO1: R9.2 U4.11 | length 969.2
  Top Layer w9.9: R9.2 3581.8,4335 v1(3680.9,4335) ; U4.11 4390.9,4515 v1(4400.9,4505)
  Bottom Layer w9.9: v1(3680.9,4335) 4110.9,4335 4310.9,4535 4370.9,4535 v1(4400.9,4505)
LO2: R13.2 U4.10 | length 715.9
  Top Layer w9.9: R13.2 v1(4328.2,4068) ; v1(4351.2,4425) 4371.2,4445 U4.10
  Bottom Layer w9.9: v1(4328.2,4068) 4328.2,4402 v1(4351.2,4425)
LO3: R17.2 U4.9 | length 1337.5
  Top Layer w9.9: v1(4171.5,3955) 4171.5,3798.2 4417.6,3552.1 R17.2 ; v1(4321.5,4505) 4351.5,4535 U4.9
  Bottom Layer w9.9: v1(4171.5,3955) 4171.5,4355 v1(4321.5,4505)
MCU_ENC_A: CN1.3 U1.13 | length 1833
  Top Layer w9.8: U1.13 5293.3,5482.3 5613.3,5482.3 v1(5633.3,5502.3)
  Bottom Layer w9.8: v1(5633.3,5502.3) 5633.3,5522.3 5981,5870 6855,5870 CN1.3
MCU_ENC_B: CN1.4 U1.40 | length 2273.8
  Top Layer w9.8: U1.40 5075.8,5053.2 5085.8,5043.2 5185.8,5043.2 v1(5195.8,5033.2) ; v1(5535.8,5353.2) 5535.8,5363.2 v1(5595.8,5423.2)
  Bottom Layer w9.8: v1(5195.8,5033.2) 5215.8,5033.2 v1(5535.8,5353.2) ; v1(5595.8,5423.2) 5595.8,5513.2 6041,5958.4 CN1.4
MCU_ENC_Z: CN1.5 U1.14 | length 1942.7
  Top Layer w9.8: U1.14 5213.6,5456.8 5273.6,5516.8 5553.6,5516.8 v1(5563.6,5506.8)
  Bottom Layer w9.8: v1(5563.6,5506.8) 6113.7,6056.8 CN1.5
PA0: C20.1 R19.1 U1.8 | length 1544.9
  Top Layer w9.8: U1.8 5519.6,5284.5 5739.6,5504.5 C20.1
  Top Layer w10: C20.1@5739.6,5504.5 v1(5769.6,5504.5) ; R19.1 5914.1,6250 6029.6,6134.5 v1(6029.6,5844.5)
  Bottom Layer w10: v1(5769.6,5504.5) 5909.6,5644.5 5909.6,5774.5 5979.6,5844.5 v1(6029.6,5844.5)
PA1: C21.1 R26.1 U1.9 | length 1573
  Top Layer w9.8: R26.1 5216.8,5931.5 v1(5236.8,5931.5) ; U1.9 5326.8,5304.2 5336.8,5314.2 5336.8,5404.2 v1(5346.8,5414.2)
  Top Layer w10: C21.1 4768.9,6379.3 R26.1
  Bottom Layer w9.8: v1(5236.8,5931.5) 5401.1,5767.1 5401.1,5468.5 v1(5346.8,5414.2)
"PWM U LO": U1.15 U4.1 | length 1269.3
  Top Layer w9.8: v1(4283.9,4717.9) 4283.9,4679.7 U4.1 ; v1(5063.9,5287.9) 5103.9,5327.9 5133.9,5327.9 5193.9,5387.9 U1.15
  Bottom Layer w9.8: v1(4283.9,4717.9) 4283.9,4727.9 4323.9,4767.9 4373.9,4767.9 4823.9,5217.9 4993.9,5217.9 v1(5063.9,5287.9)
"PWM U UP": U1.30 U4.22 | length 856.3
  Top Layer w9.8: U4.22@4351.5,4703.2 4351.5,4723.1 v1(4363.2,4734.8) ; v1(4813.2,5174.8) 4813.2,5184.8 4893.2,5264.8 U1.30
  Bottom Layer w9.8: v1(4363.2,4734.8) 4803.2,5174.8 v1(4813.2,5174.8)
"PWM V LO": U1.34 U4.2 | length 973.1
  Top Layer w9.8: v1(4257.8,4696.1) 4257.8,4666.1 4266.3,4657.7 U4.2 ; v1(4893.2,5186.1) U1.34
  Bottom Layer w9.8: v1(4257.8,4696.1) 4267.8,4686.1 4393.2,4686.1 v1(4893.2,5186.1)
"PWM V UP": U1.31 U4.23 | length 927
  Top Layer w9.8: U4.23@4331.8,4703.2 v1(4331.8,4740.4) ; v1(4843.2,5175.2) 4913.2,5245.2 U1.31
  Bottom Layer w9.8: v1(4331.8,4740.4) 4331.8,4706.6 4333.2,4705.2 4383.2,4705.2 4843.2,5165.2 v1(4843.2,5175.2)
"PWM W LO": U1.29 U4.3 | length 1076.8
  Top Layer w9.8: v1(4276.3,4757.5) 4226.3,4707.5 4226.3,4677.5 4265.8,4638 U4.3 ; v1(4743.2,5174.5) 4853.2,5284.5 U1.29
  Bottom Layer w9.8: v1(4276.3,4757.5) 4303.2,4784.5 4353.2,4784.5 v1(4743.2,5174.5)
"PWM W UP": U1.32 U4.24 | length 1086.3
  Top Layer w9.8: U4.24@4312.1,4703.2 4312.1,4725.4 4302.1,4735.5 4302.1,4775.5 v1(4362.1,4835.5) ; U1.32 4992.3,5225.5 5002.1,5235.3 5002.1,5265.5 v1(5012.1,5275.5)
  Bottom Layer w9.8: v1(4362.1,4835.5) 4802.1,5275.5 v1(5012.1,5275.5)
"SUM U": Q2.3 R10.1 R22.2 R31.2 | length 6271.7
  Top Layer w10: R10.1 4207.5,3579.3 R31.2 4342.1,3469.3 6802.1,3469.3 6832.1,3499.3 6832.1,3642.9 Q2.3 6884,3842.9 6884,4967 6784,5067 6784,5337 v1(6794,5347) ; R22.2 6004,5974.2 6004,5787 6194,5597 6314,5597 6414,5497 6414,5457 6464,5407 6714,5407 v1(6724,5417)
  Bottom Layer w10: v1(6724,5417) v1(6794,5347)
"SUM V": Q5.3 R14.1 R29.2 R32.2 | length 3819.4
  Top Layer w10: R14.1 5501.8,4626.4 5501.8,4470 R32.2 5578.1,4333.7 5994.9,4333.7 6004.9,4323.7 6074.9,4323.7 6114.9,4283.7 6588.9,4283.7 Q5.3 ; 6064.9,4323.7 v1(6064.9,4343.7) ; R29.2 6314.9,6176.6 6314.9,5703.7 v1(6244.9,5633.7)
  Bottom Layer w10: v1(6064.9,4343.7) 6244.9,4523.7 v1(6244.9,5633.7)
swclk: H1.2 U1.38
SWCLK:  | length 2544.1
  Top Layer w9.8: 5036.4,5087.7 5036.4,5122.1 5066.4,5152.1 v1(5106.4,5152.1) ; v1(5376.4,5722.1) 5656.4,6002.1 5836.4,6002.1 5886.4,6052.1 5886.4,6092.1 5936.4,6142.1 v1(5986.4,6142.1)
  Bottom Layer w9.8: v1(5106.4,5152.1) 5106.4,5162.1 5316.4,5372.1 5316.4,5572.1 5376.4,5632.1 v1(5376.4,5722.1) ; v1(5986.4,6142.1) 6602.1,6142.1 6830,6370
swdio: H1.3 U1.37
SWDIO:  | length 2604.2
  Top Layer w9.8: v1(4996.7,5122.1) 5016.7,5102.1 5016.7,5087.7 ; v1(5346.7,5702.1) 5346.7,5732.1 5626.7,6012.1 v1(5626.7,6022.1)
  Bottom Layer w9.8: v1(4996.7,5122.1) 5016.7,5122.1 5296.7,5402.1 5296.7,5652.1 v1(5346.7,5702.1) ; v1(5626.7,6022.1) 5966.7,6362.1 6722.1,6362.1 6830,6470
VB1: C17.1 D2.1 U4.20 | length 1627.2
  Top Layer w9.9: C17.1 4390.9,4901.6 U4.20@4390.9,4703.2
  Top Layer w10: C17.1 v1(4267.4,5165) ; v1(4577.4,5475) 4801.6,5699.2 D2.1
  Bottom Layer w10: v1(4267.4,5165) v1(4577.4,5475)
VB2: C18.1 D3.1 U4.17 | length 1146.8
  Top Layer w9.9: C18.1 4346.5,4364 v1(4356.5,4364) ; U4.17 4496.5,4657.7 4536.5,4617.7 4536.5,4554 v1(4526.5,4544)
  Top Layer w10: v1(4356.5,4364) 4356.5,4360.2 D3.1
  Bottom Layer w9.9: v1(4356.5,4364) 4356.5,4374 v1(4526.5,4544)
VB3: C19.1 D4.1 U4.14 | length 1391.3
  Top Layer w9.9: C19.1 3999.9,4408.6 v1(4296.5,4408.6) ; U4.14 4456.5,4598.6 4466.5,4588.6 v1(4466.5,4548.6)
  Top Layer w10: D4.1 3626.6,4462 C19.1
  Bottom Layer w9.9: v1(4296.5,4408.6) 4336.5,4448.6 4386.5,4448.6 4466.5,4528.6 v1(4466.5,4548.6)
VS1: C17.2 H2.1 Q1.3 Q2.2 R8.1 U4.18 | length 6235.5
  Top Layer w9.9: R8.1 3710,3736.8 3823.7,3850.5 3823.7,3870.5 v1(3813.7,3880.5) ; C17.2 4523.7,4823.9 v1(4523.7,4777.4) ; U4.18 4573.7,4677.4 4880.7,4370.3 4990.7,4370.3 v1(5140.7,4520.3) ; 4503.7,4677.4 v1(4503.7,4697.4) ; v1(5250.7,4520.3) 5510.7,4260.3 6010.7,4260.3 6170.7,4100.3 Q1.3
  Top Layer w10: Q1.3 6308.8,4100.3 ; v1(6468.8,4260.3) 6308.8,4100.3 ; Q2.2 6348.8,3766.5 6348.8,4060.3 6308.8,4100.3
  Bottom Layer w9.9: v1(3813.7,3880.5) 3823.7,3870.5 4163.7,3870.5 4553.7,4260.5 4553.7,4597.4 4503.7,4647.4 v1(4503.7,4697.4) 4503.7,4757.4 v1(4523.7,4777.4) ; v1(5140.7,4520.3) v1(5250.7,4520.3)
  Bottom Layer w10: v1(6468.8,4260.3) 6837,4628.5 H2.1
VS2: C18.2 H2.2 Q4.3 Q5.2 R12.1 U4.15 | length 5258.5
  Top Layer w9.9: U4.15 4458,4618.3 4498,4578.3 4498,4435.2 v1(4735,4198.2)
  Top Layer w10: C18.2 4525.8,4117.4 v1(4595,4048.2) ; v1(4775,3778.2) R12.1 4979.4,3762.6 5623.3,3762.6 Q4.3 5793.3,3852.6 v1(6037.3,3852.6) ; v1(6377.3,3892.6) 6377.3,3911.6 Q5.2
  Bottom Layer w9.9: v1(4595,4048.2) 4595,4058.2 v1(4735,4198.2)
  Bottom Layer w10: v1(4595,4048.2) 4595,4038.2 4775,3858.2 v1(4775,3778.2) ; v1(6037.3,3852.6) 6287.3,3852.6 6327.3,3892.6 v1(6377.3,3892.6) 6367.3,3902.6 6367.3,4242.6 6387.3,4262.6 6427.3,4262.6 6457.3,4232.6 6477.3,4232.6 6887,4642.3 6887,5237 H2.2
VS3: C19.2 H2.3 Q3.2 Q6.3 R16.1 U4.12 | length 6478.9
  Top Layer w9.9: v1(3839,5214.6) 3877.8,5214.6 R16.1 ; C19.2 4020.1,4193.5 4129,4084.6 4179,4084.6 4189,4094.6 4469,4094.6 v1(4479,4084.6) 4479,4044.6 4519,4004.6 4719,4004.6 4869,3854.6 5224.9,3854.6 Q3.2 ; U4.12 4410.6,4533.1 4429,4514.6 4429,4464.6 v1(4579,4314.6) ; v1@4419,4524.6 v1(4429,4524.6)
  Top Layer w10: Q3.2 5709.5,4018.8 5846.4,3881.8 6070.5,3881.8 Q6.3 ; 5716.4,4011.8 v1(5936.4,4231.8)
  Bottom Layer w9.9: v1(3839,5214.6) 3819,5234.6 3709,5234.6 3689,5214.6 3689,5154.6 4209,4634.6 4319,4634.6 v1(4429,4524.6) ; v1(4479,4084.6) 4579,4184.6 v1(4579,4314.6)
  Bottom Layer w10: v1(5936.4,4231.8) 5986.4,4231.8 6786.4,5031.8 6786.4,5301.8 6836.4,5351.8 6836.4,5386.4 H2.3
pads on no net: U1.1 U1.2 U1.3 U1.4 U1.5 U1.6 U1.10 U1.11 U1.12 U1.16 U1.17 U1.18 U1.20 U1.22 U1.25 U1.26 U1.27 U1.28 U1.33 U1.39 U1.41 U1.42 U1.43 U1.44 U1.46 U4.5 U4.7 U4.8 U4.21 U6.2

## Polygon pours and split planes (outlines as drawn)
GND on Bottom Layer (solid, remove dead copper, pour order 2): 3295,6955 3295,3155 7190,3155 7190,6955
GND on Top Layer (solid, remove dead copper, pour order 2): 3000,6975 3000,3000 7825,3000 7825,6975

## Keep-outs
Board Outline Layer:
  the board outline again, w10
